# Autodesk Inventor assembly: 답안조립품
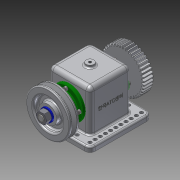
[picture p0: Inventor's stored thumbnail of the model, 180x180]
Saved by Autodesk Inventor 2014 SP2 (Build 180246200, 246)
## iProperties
Created: 2018-11
Part Number: 답안조립품
Document SubType Name: Assembly
Designer: 거성
Author: 거성
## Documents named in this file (13)
- C:\Users\거성\Desktop\481108V1007\답안조립품.iam
- C:\Users\거성\Desktop\481108V1007\본체.ipt
- C:\Users\거성\Desktop\481108V1007\축.ipt
- C:\Users\거성\Desktop\481108V1007\키 5x5x12.ipt
- C:\Users\거성\Desktop\481108V1007\베어링 6203.ipt
- C:\Users\거성\Desktop\481108V1007\부시.ipt
- C:\Users\거성\Desktop\481108V1007\커버.ipt
- C:\Users\거성\Desktop\481108V1007\오일 실 26 38 8.ipt
- C:\Users\거성\Desktop\481108V1007\볼트 M4.ipt
- C:\Users\거성\Desktop\481108V1007\V벨트풀리.ipt
- C:\Users\거성\Desktop\481108V1007\스퍼기어.ipt
- C:\Users\거성\Desktop\481108V1007\와셔 12x24.ipt
- C:\Users\거성\Desktop\481108V1007\너트 M12x1.25.ipt
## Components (1 placed, 1 different names)
1. V벨트풀리:1 — 각도:9
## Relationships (1: Angle 1)
- 각도:9 [Angle]: V벨트풀리:1
